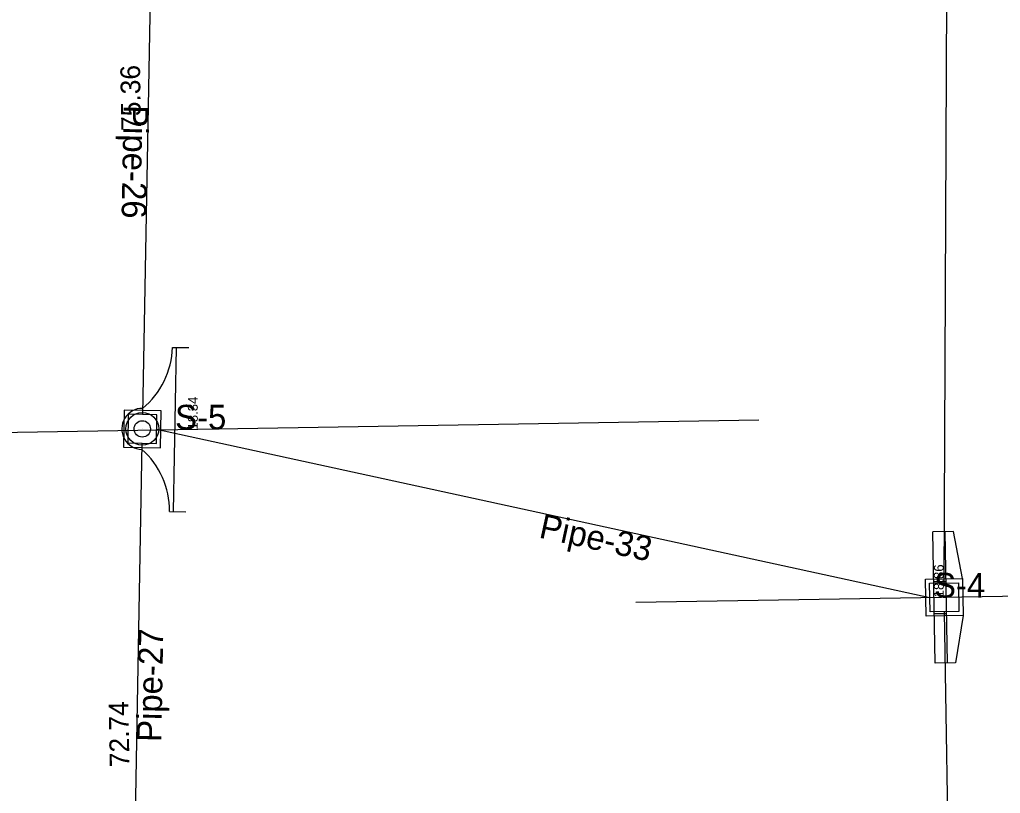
# Model space of a CAD drawing. Extents: x 925371 to 925937, y 853654 to 858024.
# Drawn here: x 925740.2 to 925859.8, y 853799.4 to 853893.7 of the extents above; entities that cross this region are included whole.
import ezdxf

# ---------------------------------------------------------------- set-up
doc = ezdxf.new("R2010")
doc.units = 0
for name, color, linetype in [('GPKDrBack_dp', 7, 'Continuous'), ('GPKDrBottom_dp', 7, 'Continuous'), ('GPKDrCellIns_dp', 7, 'Continuous'), ('GPKDrCentroid_dp', 7, 'Continuous'), ('GPKDrFront_dp', 7, 'Continuous'), ('GPKDrPipe_dp', 7, 'Continuous'), ('GPKDrPipeCir_dp', 7, 'Continuous'), ('InletBottomP', 7, 'Continuous'), ('InletCurb', 7, 'Continuous'), ('Miscellaneous6', 7, 'Continuous'), ('NonPlottingEle_dp', 7, 'Continuous'), ('PipeCulvert', 7, 'Continuous')]:
    doc.layers.add(name, color=color, linetype=linetype)

msp = doc.modelspace()

# ---------------------------------------------------------------- linework, layer by layer
at = {"layer": 'GPKDrBack_dp'}
for p, q in [((925752.7, 853843.82), (925752.7, 853843.82)), ((925753.45, 853843.81), (925753.45, 853843.81)), ((925854.71, 853823.28), (925854.71, 853823.28)), ((925855.21, 853823.28), (925855.21, 853823.28))]:
    msp.add_line(p, q, dxfattribs=at)
at = {"layer": 'GPKDrBottom_dp'}
for p, q in [((925753.48, 853845.56), (925753.48, 853845.56)), ((925753.81, 853845.22), (925753.81, 853845.22)), ((925755.23, 853845.53), (925755.23, 853845.53)), ((925755.24, 853845.78), (925755.24, 853845.78)), ((925756.64, 853845.17), (925756.64, 853845.17)), ((925756.98, 853845.5), (925756.98, 853845.5)), ((925753.2, 853843.81), (925753.2, 853843.81)), ((925753.45, 853843.81), (925753.45, 853843.81)), ((925755.2, 853843.78), (925755.2, 853843.78)), ((925755.2, 853843.78), (925755.2, 853843.78)), ((925756.95, 853843.75), (925756.95, 853843.75)), ((925757.2, 853843.74), (925757.2, 853843.74)), ((925753.42, 853842.06), (925753.42, 853842.06)), ((925753.76, 853842.39), (925753.76, 853842.39)), ((925755.17, 853842.03), (925755.17, 853842.03)), ((925755.17, 853841.78), (925755.17, 853841.78)), ((925756.59, 853842.34), (925756.59, 853842.34)), ((925756.92, 853842), (925756.92, 853842)), ((925851.18, 853824.97), (925851.18, 853824.97)), ((925851.18, 853824.97), (925851.18, 853824.97)), ((925852.93, 853825), (925852.93, 853825)), ((925852.93, 853825), (925852.93, 853825)), ((925854.68, 853825.03), (925854.68, 853825.03)), ((925854.68, 853825.02), (925854.68, 853825.02)), ((925851.21, 853823.22), (925851.21, 853823.22)), ((925851.21, 853823.22), (925851.21, 853823.22)), ((925852.96, 853823.25), (925852.96, 853823.25)), ((925852.96, 853823.25), (925852.96, 853823.25)), ((925854.71, 853823.28), (925854.71, 853823.28)), ((925854.71, 853823.28), (925854.71, 853823.28)), ((925851.24, 853821.47), (925851.24, 853821.47)), ((925851.24, 853821.47), (925851.24, 853821.47)), ((925852.99, 853821.5), (925852.99, 853821.5)), ((925852.99, 853821.5), (925852.99, 853821.5)), ((925854.74, 853821.53), (925854.74, 853821.53)), ((925854.74, 853821.53), (925854.74, 853821.53))]:
    msp.add_line(p, q, dxfattribs=at)
at = {"layer": 'GPKDrCellIns_dp'}
for p, q in [((925755.2, 853843.78), (925755.2, 853843.78)), ((925760.7, 853843.68), (925760.7, 853843.68)), ((925851.71, 853823.22), (925851.71, 853823.22)), ((925852.96, 853823.25), (925852.96, 853823.25))]:
    msp.add_line(p, q, dxfattribs=at)
at = {"layer": 'GPKDrCentroid_dp'}
for p, q in [((925755.2, 853843.78), (925755.2, 853843.78)), ((925852.96, 853823.25), (925852.96, 853823.25))]:
    msp.add_line(p, q, dxfattribs=at)
at = {"layer": 'GPKDrFront_dp'}
for p, q in [((925756.95, 853843.75), (925756.95, 853843.75)), ((925760.7, 853843.68), (925760.7, 853843.68)), ((925851.21, 853823.22), (925851.21, 853823.22)), ((925851.71, 853823.22), (925851.71, 853823.22))]:
    msp.add_line(p, q, dxfattribs=at)
at = {"layer": 'GPKDrPipe_dp'}
for p, q in [((925753.83, 853845.24), (925753.83, 853845.24)), ((925754.48, 853845.64), (925754.48, 853845.64)), ((925755.23, 853845.53), (925755.23, 853845.53)), ((925755.24, 853845.78), (925755.24, 853845.78)), ((925756.04, 853845.59), (925756.04, 853845.59)), ((925756.66, 853845.15), (925756.66, 853845.15)), ((925753.2, 853843.81), (925753.2, 853843.81)), ((925753.39, 853844.62), (925753.39, 853844.62)), ((925753.45, 853843.81), (925753.45, 853843.81)), ((925756.95, 853843.75), (925756.95, 853843.75)), ((925757.07, 853844.5), (925757.07, 853844.5)), ((925757.2, 853843.74), (925757.2, 853843.74)), ((925753.34, 853843.06), (925753.34, 853843.06)), ((925757.02, 853842.94), (925757.02, 853842.94)), ((925753.74, 853842.41), (925753.74, 853842.41)), ((925754.36, 853841.96), (925754.36, 853841.96)), ((925755.17, 853842.03), (925755.17, 853842.03)), ((925755.17, 853841.78), (925755.17, 853841.78)), ((925755.92, 853841.91), (925755.92, 853841.91)), ((925756.57, 853842.32), (925756.57, 853842.32)), ((925852.93, 853825), (925852.93, 853825)), ((925852.93, 853825), (925852.93, 853825)), ((925851.21, 853823.22), (925851.21, 853823.22)), ((925851.21, 853823.22), (925851.21, 853823.22)), ((925854.71, 853823.28), (925854.71, 853823.28)), ((925854.71, 853823.28), (925854.71, 853823.28)), ((925852.99, 853821.5), (925852.99, 853821.5)), ((925852.99, 853821.5), (925852.99, 853821.5))]:
    msp.add_line(p, q, dxfattribs=at)
at = {"layer": 'GPKDrPipeCir_dp'}
msp.add_lwpolyline([(925851.24, 853821.47), (925851.18, 853824.97), (925854.68, 853825.02), (925854.74, 853821.53)], close=True, dxfattribs=at)
msp.add_circle((925755.2, 853843.78), 2, dxfattribs=at)
at = {"layer": 'InletBottomP'}
for points in [[(925752.99, 853846.07), (925752.91, 853841.57), (925757.41, 853841.49), (925757.49, 853845.99)], [(925756.98, 853845.5), (925753.48, 853845.56), (925753.42, 853842.06), (925756.92, 853842)], [(925855.17, 853825.53), (925855.25, 853821.03), (925850.75, 853820.96), (925850.67, 853825.46)], [(925851.18, 853824.97), (925854.68, 853825.03), (925854.74, 853821.53), (925851.24, 853821.47)]]:
    msp.add_lwpolyline(points, close=True, dxfattribs=at)
at = {"layer": 'InletCurb'}
for p, q in [((925758.88, 853853.71), (925760.88, 853853.68)), ((925759.02, 853833.71), (925759.38, 853853.71)), ((925758.52, 853833.72), (925760.52, 853833.68)), ((925854.08, 853831.27), (925851.58, 853831.22)), ((925851.85, 853815.23), (925851.58, 853831.22)), ((925853.35, 853815.25), (925853.08, 853831.25)), ((925855.17, 853825.53), (925854.08, 853831.27)), ((925851.68, 853825.17), (925853.18, 853825.2)), ((925855.17, 853825.53), (925855.25, 853821.03)), ((925851.75, 853821.27), (925853.24, 853821.29)), ((925855.25, 853821.03), (925854.35, 853815.27)), ((925854.35, 853815.27), (925851.85, 853815.23))]:
    msp.add_line(p, q, dxfattribs=at)
msp.add_circle((925755.2, 853843.78), 1, dxfattribs=at)
for centre, radius, start, end in [((925748.88, 853853.99), 10, 309.512, 358.4025), ((925755.2, 853843.78), 2.5, 88.9741, 268.9741), ((925748.52, 853833.8), 10, 359.5458, 48.4363)]:
    msp.add_arc(centre, radius, start, end, dxfattribs=at)
at = {"layer": 'Miscellaneous6'}
for p, q in [((925830.34, 853844.86), (925618.58, 853841.26)), ((925936.82, 853824.67), (925815.37, 853822.61))]:
    msp.add_line(p, q, dxfattribs=at)
at = {"layer": 'PipeCulvert'}
for p, q in [((925852.93, 853825), (925853.77, 853994.12)), ((925756.63, 853920.87), (925755.23, 853845.53)), ((925756.95, 853843.75), (925851.21, 853823.22)), ((925753.88, 853769.3), (925755.17, 853842.03)), ((925854.87, 853711.01), (925852.99, 853821.5))]:
    msp.add_line(p, q, dxfattribs=at)

# ---------------------------------------------------------------- texts
at = {"layer": 'NonPlottingEle_dp'}
for s, height, rotation, p in [('75.36', 2.4, 90.9741, (925755.05, 853880.11)), ('Pipe-26', 3, 268.9402, (925752.93, 853883.26)), ('18.34', 1.2, 90, (925761.96, 853843.7)), ('Pipe-33', 3, 347.7119, (925803.44, 853830.55)), ('18.86', 1.2, 90, (925852.9, 853823.25)), ('Pipe-27', 3, 88.9799, (925757.52, 853805.61)), ('72.74', 2.4, 90.9741, (925753.64, 853802.58))]:
    msp.add_text(s, height=height, rotation=rotation, dxfattribs=at).set_placement(p)
for s, p in [('S-5', (925759.2, 853843.71)), ('S-4', (925851.71, 853823.22))]:
    msp.add_text(s, height=3, dxfattribs=at).set_placement(p)

doc.saveas('drawing.dxf')
